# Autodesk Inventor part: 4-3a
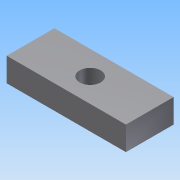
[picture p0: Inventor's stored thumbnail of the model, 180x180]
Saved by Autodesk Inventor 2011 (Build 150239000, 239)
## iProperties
Created: 2014-03
Part Number: 4-3a
Document SubType Name: Modeling
Designer: Administrator
Density: 1 g/cm^3
Author: Administrator
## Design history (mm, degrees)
sketch "草图1"
  geometry: L1 (-50, 20)-(50, 20); L2 (50, 20)-(50, -20); L3 (50, -20)-(-50, -20); L4 (-50, -20)-(-50, 20); 3 further points
  constraints: 8 end point, 2 midpoint, 2 parallel, 1 horizontal, 1 horizontal alignment, 1 perpendicular, 1 vertical alignment
  dimensions: "d0" = 100 distance of L2.end L3.end; "d1" = 40 distance of L3.end L1.start
extrude "拉伸1" new body sketch "草图1" distance "d2" = 20; taper "d3" = 0 deg
hole "Hole1" diameter "d6" = 17.6; stored, may be unused: countersink angle "d10" = 90 deg, drill point angle "d12" = 118 deg; dims "d4" = 20, "d5" = 50, "d7" = 6, "d8" = 4, "d9" = 2, "d11" = 8
node "实体1"
